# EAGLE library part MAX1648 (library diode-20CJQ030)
Maxim's MAX1647 Chemistry-Independent Battery Chargers General Description: The MAX1647/MAX1648 provide the power control necessary to charge batteries of any chemistry. In the MAX1647, all charging functions are controlled through the Intel System Management Bus (SMBus?) interface. The SMBus 2-wire serial interface sets the charge voltage and current, and provides thermal status information. The MAX1647 functions as a level 2 charger, compliant with the Duracell/Intel Smart Battery Charger Specification. The MAX1648 omits the SMBus serial interface, and instead sets the charge voltage and current proportional to the voltage applied to external control pins. In addition to the feature set required for a level 2 charger, the MAX1647 generates interrupts to signal the host when power is applied to the charger or a battery is installed or removed. Additional status bits allow the host to check whether the charger has enough input voltage, and whether the voltage on or current into the battery is being regulated. This allows the host to determine when lithiumion batteries have completed charge without interrogating the battery. The MAX1647 is available in a 20-pin SSOP with a 2mm profile height. The MAX1648 is available in a 16-pin SO package. Features: Charges Any Battery Chemistry: Li-Ion, NiCd, NiMH, Lead Acid, etc. Intel SMBus 2-Wire Serial Interface (MAX1647) Intel/Duracell Level 2 Smart Battery Compliant (MAX1647) 4A, 2A, or 1A Maximum Battery-Charge Current 11-Bit Control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
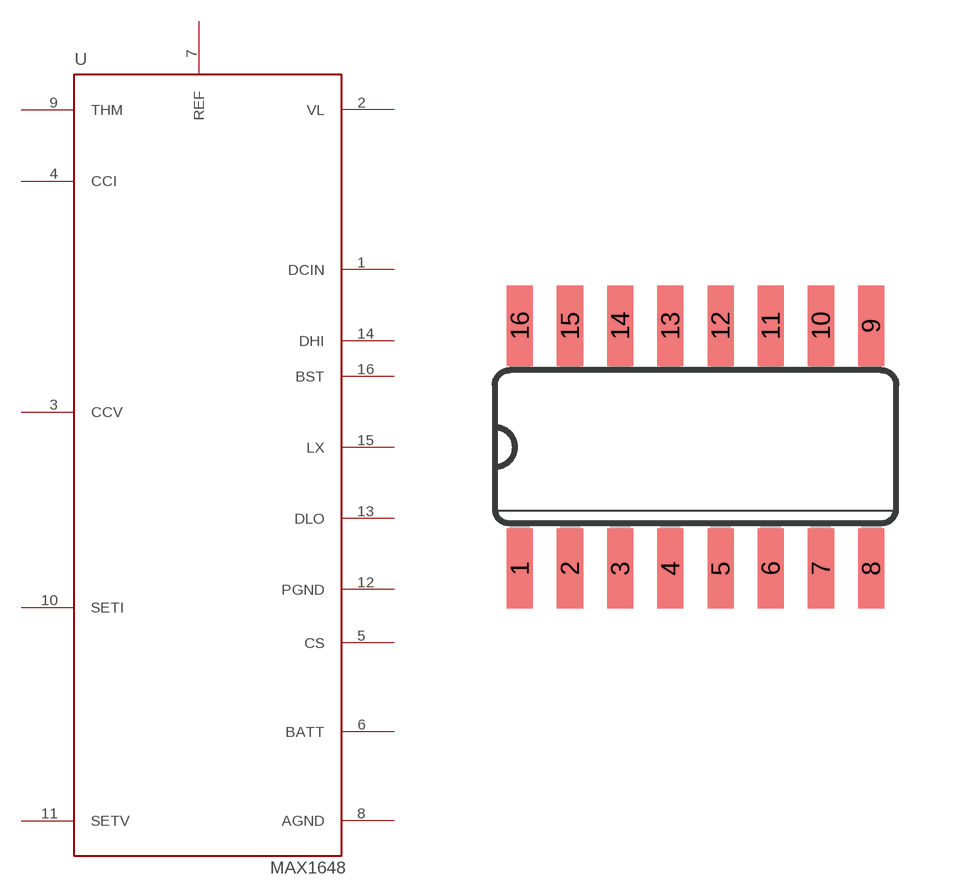
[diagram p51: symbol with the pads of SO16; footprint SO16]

Designator prefix U

## MAX1648  [SO16]
1  DCIN
2  VL
3  CCV
4  CCI
5  CS
6  BATT
7  REF
8  AGND
9  THM
10  SETI
11  SETV
12  PGND
13  DLO
14  DHI
15  LX
16  BST

## Footprint SO16 (pad centres in mm)
Small Outline Package
smd 0.66 x 2.032: 1 -4.445,-3.073; 2 -3.175,-3.073; 3 -1.905,-3.073; 4 -0.635,-3.073; 5 0.635,-3.073; 6 1.905,-3.073; 7 3.175,-3.073; 8 4.445,-3.073; 9 4.445,3.073; 10 3.175,3.073; 11 1.905,3.073; 12 0.635,3.073; 13 -0.635,3.073; 14 -1.905,3.073; 15 -3.175,3.073; 16 -4.445,3.073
